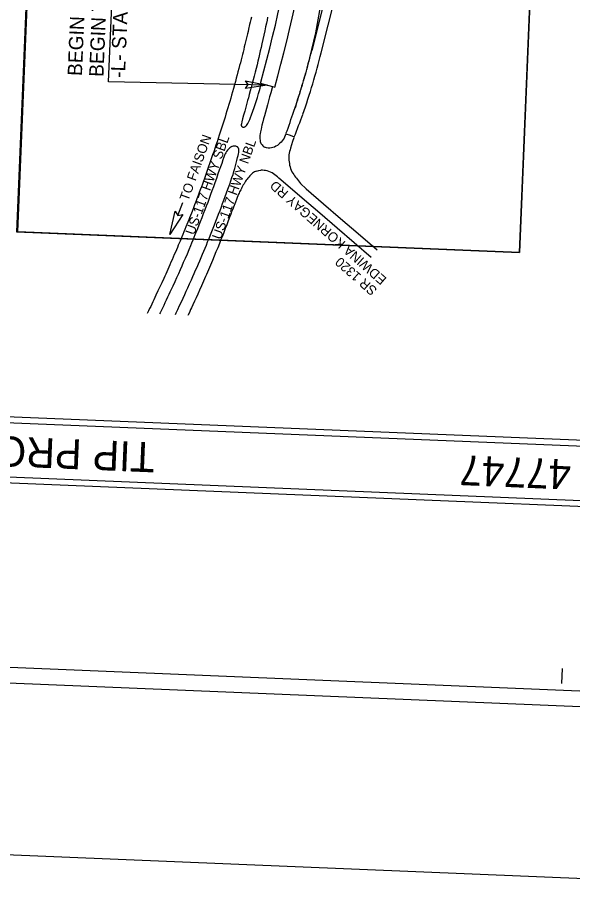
# Model space of a CAD drawing. Extents: x 2264506 to 2267635, y 507918 to 512596.
# Drawn here: x 2265694 to 2266855, y 507918 to 509740 of the extents above; entities that cross this region are included whole.
import ezdxf

# ---------------------------------------------------------------- set-up
doc = ezdxf.new("R2010")
doc.units = 0
for name, color, linetype in [('COGO Default Parcel', 7, 'Continuous'), ('Default', 7, 'Continuous'), ('Exist Structure Minor Drop Inlet Cogo Number', 7, 'Continuous'), ('Matchline', 7, 'Continuous'), ('Prop EOT Dash', 7, 'Continuous'), ('Prop Guardrail', 7, 'Continuous'), ('Prop Horizontal Alignment Station Label', 7, 'Continuous'), ('Prop Horizontal Alignment Tick Label', 7, 'Continuous'), ('Prop Horizontal Alignment Tick Large', 7, 'Continuous'), ('Prop Lane Arrow CELL', 7, 'Continuous'), ('Prop Structure Anchor Unit CELL', 7, 'Continuous'), ('Scratch_Level_1', 7, 'Continuous')]:
    doc.layers.add(name, color=color, linetype=linetype)

msp = doc.modelspace()

# ---------------------------------------------------------------- linework, layer by layer
at = {"layer": 'COGO Default Parcel'}
msp.add_lwpolyline([(2266744.1, 509248.2), (2266800.3, 510607.5), (2265959.7, 510642.3), (2265949.8, 510403.2), (2265738.5, 510412), (2265692.2, 509291.7)], close=True, dxfattribs=at)
at = {"layer": 'Exist Structure Minor Drop Inlet Cogo Number'}
for p, q in [((2265884.5, 509605.1), (2265907.1, 510153.7)), ((2266216, 509598.3), (2265884.5, 509605.1)), ((2266029.4, 509325.8), (2266040.1, 509353))]:
    msp.add_line(p, q, dxfattribs=at)
at = {"layer": 'Matchline'}
msp.add_line((2264698.7, 508031), (2267446.4, 507917.5), dxfattribs=at)
at = {"layer": 'Prop EOT Dash'}
msp.add_lwpolyline([(2265695, 509291.6), (2265813.1, 512149.6), (2266862.2, 512106.3), (2266744.1, 509248.2)], close=True, dxfattribs=at)
at = {"layer": 'Prop Guardrail'}
for p, q in [((2266377.5, 509938.8), (2266309.8, 509670.6)), ((2266329.1, 509665.7), (2266396, 509930.1)), ((2266202.5, 509602), (2266204.4, 509601.5)), ((2266255.5, 509496.7), (2266264.4, 509493.4)), ((2266264.4, 509493.4), (2266272.8, 509490.2))]:
    msp.add_line(p, q, dxfattribs=at)
msp.add_lwpolyline([(2266204.4, 509601.5), (2266227.6, 509595.1), (2266232.4, 509593.8)], dxfattribs=at)
for centre, radius, start, end in [((2262840, 510521.8), 3486, 344.7422, 357.6342), ((2262840, 510521.8), 3517, 344.7004, 357.6342), ((2264768.3, 510060.4), 1590, 341.0347, 345.8113), ((2264768.3, 510060.4), 1610, 341.0347, 345.8113), ((2263436.2, 510359.2), 2868, 344.6915, 344.7422), ((2264763.4, 510046.5), 1590.2, 339.7742, 341.5648), ((2264779.6, 510090), 1609.2, 338.1129, 339.9041)]:
    msp.add_arc(centre, radius, start, end, dxfattribs=at)
at = {"layer": 'Prop Horizontal Alignment Station Label'}
for p, q in [((2266922.1, 508853.6), (2264836.3, 508939.8)), ((2267383.7, 508822), (2264835.8, 508927.3)), ((2266832.4, 508348.1), (2266833.7, 508379.3)), ((2266832.4, 508348.1), (2266833.7, 508379.3))]:
    msp.add_line(p, q, dxfattribs=at)
for points in [[(2264818.2, 508802.9), (2267391, 508696.6)], [(2264818.2, 508802.9), (2267391, 508696.6)], [(2264831.2, 508814.9), (2267379, 508709.6)]]:
    msp.add_lwpolyline(points, dxfattribs=at)
at = {"layer": 'Prop Horizontal Alignment Tick Label'}
msp.add_lwpolyline([(2267406.5, 508310.6), (2267578.5, 512473.3), (2264943, 512582.2), (2264771, 508419.5)], close=True, dxfattribs=at)
at = {"layer": 'Prop Horizontal Alignment Tick Large'}
msp.add_lwpolyline([(2264887.3, 512595.8), (2264713.6, 508389.4), (2267461.2, 508275.9), (2267635, 512482.3)], close=True, dxfattribs=at)
at = {"layer": 'Prop Lane Arrow CELL'}
for p, q in [((2266339.5, 509830.1), (2266317, 509707.7)), ((2266254.7, 509494.8), (2266251.8, 509487)), ((2266251.8, 509487), (2266250, 509484.5)), ((2266269.4, 509480.4), (2266265, 509466.5)), ((2266272.1, 509488.2), (2266269.4, 509480.4))]:
    msp.add_line(p, q, dxfattribs=at)
for points in [[(2266183.1, 509740.4), (2266181.9, 509735), (2266180.7, 509729.8), (2266179.6, 509724.7), (2266177.3, 509715), (2266176.2, 509710.2), (2266175, 509705.1), (2266173.7, 509699.8), (2266172.4, 509694.3), (2266171, 509688.7), (2266169.7, 509683.2), (2266168.4, 509677.8), (2266167.1, 509672.6), (2266165.8, 509667.3), (2266164.4, 509661.9), (2266163, 509656.4), (2266161.6, 509650.8), (2266160.1, 509645), (2266158.6, 509639), (2266156.9, 509632.7), (2266155.2, 509626.1), (2266153.4, 509619.4), (2266151.6, 509612.5), (2266149.7, 509605.5), (2266147.7, 509598.4), (2266145.7, 509591.2), (2266143.7, 509584.2), (2266141.8, 509577.4), (2266139.9, 509570.7), (2266138, 509564.1), (2266136, 509557.5), (2266134.1, 509550.9), (2266132.1, 509544.3), (2266130.1, 509537.8), (2266128.1, 509531.4), (2266126.2, 509525.1), (2266124.2, 509518.9), (2266122.2, 509512.7), (2266120.2, 509506.4), (2266118.1, 509499.9), (2266116, 509493.3), (2266113.8, 509486.5), (2266111.5, 509479.7), (2266109.2, 509472.8), (2266106.8, 509465.9), (2266104.5, 509459), (2266102.2, 509452.4), (2266100, 509446.1), (2266097.9, 509440), (2266095.9, 509434), (2266093.8, 509427.9), (2266091.6, 509421.8), (2266089.4, 509415.5), (2266087.2, 509409.3), (2266085, 509403.2), (2266082.9, 509397.2), (2266080.8, 509391.4), (2266078.6, 509385.5), (2266076.4, 509379.6), (2266074.2, 509373.7), (2266071.9, 509367.7), (2266069.3, 509360.7), (2266067.8, 509356.7), (2266064.4, 509347.9), (2266061.3, 509339.8), (2266057.8, 509330.7), (2266055.9, 509325.9), (2266054, 509321.2), (2266052.2, 509316.4), (2266050.3, 509311.7), (2266048.4, 509306.9), (2266046.3, 509301.9), (2266044.3, 509296.8), (2266042.1, 509291.5), (2266039.9, 509286.3), (2266037.9, 509281.3), (2266034.1, 509272.3), (2266030.4, 509263.5), (2266028.5, 509258.9), (2266026.4, 509254.1), (2266024.3, 509249.2), (2266022, 509244.1), (2266019.8, 509238.9), (2266017.4, 509233.4), (2266015, 509228), (2266012.7, 509222.8), (2266010.5, 509217.8), (2266008.3, 509213), (2266006.2, 509208.2), (2266004, 509203.5), (2266001.9, 509198.8), (2265999.8, 509194.1), (2265995.6, 509185), (2265991.7, 509176.6), (2265987.8, 509168.3), (2265983.6, 509159.2), (2265981.5, 509154.5), (2265979.3, 509149.9), (2265977.1, 509145.2), (2265974.9, 509140.5), (2265972.6, 509135.9), (2265970.4, 509131.2), (2265968.2, 509126.7), (2265966, 509122.1), (2265965.5, 509121.1)], [(2266217.1, 509740.3), (2266215.9, 509734.1), (2266214.5, 509727.4), (2266212.9, 509719.9), (2266211.1, 509711.6), (2266209.2, 509702.4), (2266207.2, 509693.2), (2266205.3, 509684.6), (2266203.5, 509676.8), (2266201.9, 509669.7), (2266200.3, 509662.9), (2266198.6, 509655.7), (2266196.8, 509648.3), (2266195, 509640.7), (2266193, 509632.9), (2266191, 509625), (2266189, 509617.1), (2266186.9, 509609.1), (2266184.8, 509601.2), (2266182.8, 509593.5), (2266180.8, 509586), (2266178.8, 509578.7), (2266177, 509571.9), (2266175.3, 509565.9), (2266173.9, 509560.7), (2266171.5, 509552.1), (2266169.2, 509543.7), (2266166.9, 509535.3), (2266164.8, 509527.8), (2266163.1, 509521.6), (2266162.2, 509517.5), (2266161.9, 509515.4), (2266161.8, 509514.7), (2266161.8, 509514.1), (2266161.9, 509513.6), (2266162, 509513.2), (2266162.2, 509512.8), (2266162.4, 509512.4), (2266162.6, 509512.1), (2266162.9, 509511.8), (2266163.3, 509511.6), (2266163.7, 509511.3), (2266164.8, 509510.8), (2266165.6, 509510.5), (2266165.8, 509510.5), (2266166.4, 509510.4), (2266167.3, 509510.4), (2266167.8, 509510.4), (2266168.3, 509510.5), (2266168.9, 509510.7), (2266169.5, 509511), (2266170.6, 509511.8), (2266171.9, 509512.8), (2266172.6, 509513.4), (2266173.3, 509514.1), (2266174.6, 509516), (2266176, 509518.3), (2266177.2, 509520.8), (2266178.5, 509523.5), (2266179.7, 509526.4), (2266181.2, 509530.4), (2266183.4, 509536.4), (2266186, 509543.7), (2266189, 509551.7), (2266191.7, 509559.5), (2266193.9, 509566.2), (2266195.8, 509572.2), (2266196.7, 509575.2), (2266198.4, 509580.9), (2266200, 509586.6), (2266201.6, 509592.1), (2266203.2, 509597.7), (2266204.2, 509601.5)], [(2266227.4, 509595.2), (2266223.8, 509582.1), (2266221.4, 509573.5), (2266219.1, 509565.2), (2266216.8, 509557), (2266214.6, 509549), (2266212.4, 509541.3), (2266210.3, 509534), (2266208.5, 509527.5), (2266207, 509521.4), (2266205.3, 509514.3), (2266203.4, 509506.3), (2266202.1, 509500.3), (2266201.5, 509496.4), (2266201.1, 509493.4), (2266200.9, 509491), (2266200.8, 509489.3), (2266200.8, 509488.1), (2266201, 509486), (2266201.4, 509483.1), (2266201.8, 509480.6), (2266202.4, 509478.6), (2266203, 509477), (2266203.3, 509476.4), (2266204.2, 509475), (2266205.5, 509473.2), (2266207.2, 509471.2), (2266209.2, 509469.2)], [(2266024.3, 509118.6), (2266025.9, 509122.1), (2266029.5, 509129.7), (2266033.2, 509137.6), (2266036.9, 509145.5), (2266040.4, 509153.1), (2266043.7, 509160.4), (2266047, 509167.5), (2266050.4, 509174.9), (2266054.1, 509183.2), (2266057.7, 509191.3), (2266060.8, 509198.2), (2266063.6, 509204.7), (2266066.6, 509211.3), (2266069.5, 509217.9), (2266072.5, 509224.6), (2266075.4, 509231.3), (2266078.3, 509238.1), (2266081.1, 509244.8), (2266083.8, 509251.2), (2266086.4, 509257.5), (2266089, 509263.7), (2266091.7, 509270.4), (2266094.7, 509277.9), (2266097.7, 509285.4), (2266100.5, 509292.3), (2266103.2, 509299), (2266105.9, 509306.2), (2266108.8, 509313.6), (2266111.7, 509321.1), (2266114.7, 509328.7), (2266117.6, 509336.2), (2266120.4, 509343.6), (2266123.1, 509350.8), (2266125.7, 509358.1), (2266128.6, 509365.7), (2266131.4, 509373.3), (2266134, 509380.5), (2266135.3, 509383.9), (2266137.8, 509391), (2266140.3, 509398.3), (2266142.6, 509405.1), (2266144.8, 509411.6), (2266146.7, 509417.9), (2266148.4, 509424), (2266149.9, 509429.7), (2266151.3, 509435.1), (2266152.8, 509440.8), (2266154.3, 509446.7), (2266155.4, 509451.4), (2266156.2, 509454.8), (2266156.7, 509457.7), (2266157, 509460), (2266157.1, 509462.1), (2266157, 509463.9), (2266156.9, 509464.7), (2266156.7, 509465.4), (2266156.5, 509466), (2266155.9, 509467.1), (2266155.2, 509468.1), (2266154.8, 509468.6), (2266154.3, 509469), (2266153.7, 509469.4), (2266152.3, 509470), (2266151, 509470.5), (2266150.4, 509470.7), (2266149.7, 509470.8), (2266149, 509470.9), (2266147.2, 509470.8), (2266145.2, 509470.6), (2266143.2, 509470), (2266142.2, 509469.6), (2266141.2, 509469.2), (2266140.3, 509468.6), (2266138.4, 509467.3), (2266136.7, 509465.7), (2266135.1, 509464), (2266133.3, 509461.9), (2266131.4, 509459.4), (2266129.8, 509457), (2266128.6, 509454.7), (2266127.3, 509451.6), (2266125.6, 509447.4), (2266123.6, 509441.7), (2266121.1, 509434.6), (2266118.6, 509427.6), (2266116.1, 509420.6), (2266113.2, 509412.5), (2266110, 509403.1), (2266106.8, 509394), (2266103.7, 509385.3), (2266100.8, 509377.1), (2266098, 509369.3), (2266095, 509361.3), (2266091.9, 509353.2), (2266088.8, 509345.2), (2266085.7, 509337.3), (2266082.6, 509329.1), (2266079.4, 509320.7), (2266076.3, 509312.8), (2266073.4, 509305.4), (2266070.4, 509297.8), (2266067.1, 509289.9), (2266065.2, 509285.2), (2266063, 509279.9), (2266060.6, 509274), (2266058.2, 509268.1), (2266056, 509262.7), (2266052.2, 509253.7), (2266048.6, 509245.3), (2266044.7, 509236.2), (2266040.8, 509227.3), (2266037.5, 509219.6), (2266034.2, 509212.2), (2266030.6, 509204), (2266026.7, 509195.4), (2266022.8, 509186.9), (2266018.9, 509178.4), (2266015, 509170), (2266012.9, 509165.6), (2266010.6, 509160.6), (2266008, 509155.1), (2266005.2, 509149.2), (2266002.4, 509143.2), (2265999.9, 509138), (2265995.8, 509129.5), (2265992.2, 509122.2), (2265991.2, 509120)], [(2266209.2, 509469.2), (2266209.2, 509469.2), (2266210.5, 509468.8)], [(2266193.9, 509418.5), (2266191.8, 509417.7), (2266189.5, 509416.7), (2266187.3, 509415.5), (2266185.5, 509414.3), (2266183.8, 509412.8), (2266181.8, 509410.8), (2266179.7, 509408.5), (2266177.7, 509406.1), (2266175.7, 509403.7), (2266174.1, 509401.6), (2266172.6, 509399.6), (2266171, 509397.3), (2266169.4, 509394.8), (2266167.8, 509392.2), (2266166.3, 509389.6), (2266164.9, 509387), (2266163.5, 509384.5), (2266162.2, 509382), (2266160.9, 509379.6), (2266159.8, 509377.3), (2266158.6, 509374.9), (2266157.5, 509372.5), (2266156.4, 509370), (2266155.2, 509367), (2266153.8, 509363.6), (2266152.1, 509359.3), (2266149.9, 509353.7), (2266147, 509346.4), (2266143.7, 509337.9), (2266141.9, 509333.2), (2266140.1, 509328.3), (2266138.3, 509323.5), (2266134.9, 509314.5), (2266131.8, 509306.4), (2266128.7, 509298.3), (2266125.5, 509290.1), (2266122.5, 509282.5), (2266119.6, 509275.4), (2266116.4, 509267.3), (2266112.7, 509258.3), (2266109.1, 509249.5), (2266105.7, 509241.1), (2266101.9, 509231.9), (2266099.8, 509226.9), (2266097.7, 509221.9), (2266095.6, 509217), (2266093.6, 509212.2), (2266091.6, 509207.5), (2266089.5, 509202.8), (2266087.5, 509198), (2266085.3, 509193.2), (2266083.1, 509188.3), (2266080.9, 509183.4), (2266078.8, 509178.6), (2266074.7, 509169.5), (2266071, 509161.2), (2266067.7, 509153.8), (2266064.4, 509146.7), (2266060.8, 509139.1), (2266057.7, 509132.6), (2266056.1, 509129.1), (2266054.2, 509125.3), (2266050.8, 509117.8), (2266050.6, 509117.5)], [(2266193.9, 509418.5), (2266198.9, 509419.5), (2266203.3, 509420.4)], [(2266434, 509238), (2266398.3, 509268.5), (2266362.3, 509299.5), (2266326.6, 509330.3), (2266289.5, 509362.1), (2266259.2, 509388), (2266240.4, 509404)], [(2266279.3, 509400.9), (2266285.8, 509392.6), (2266298, 509381.3), (2266334, 509350.3), (2266369.7, 509319.7), (2266406.6, 509288.1), (2266446.4, 509253.8)]]:
    msp.add_lwpolyline(points, dxfattribs=at)
for points in [[(2266317, 509707.7), (2266306.1, 509661.1), (2266300, 509636.9), (2266296.8, 509624.8), (2266293.4, 509612.8), (2266286.6, 509589.9), (2266279.6, 509567), (2266274.7, 509551)], [(2266250, 509484.5), (2266240.2, 509474.2), (2266228.4, 509467.6), (2266215.1, 509467.1), (2266210.5, 509468.8)], [(2266265, 509466.5), (2266261.7, 509452.5), (2266262.1, 509437.7), (2266265.1, 509423.7), (2266271.8, 509411.2), (2266279.3, 509400.9)], [(2266240.4, 509404), (2266229.7, 509412.6), (2266216.1, 509418.9), (2266203.3, 509420.4)]]:
    msp.add_spline(points, degree=3, dxfattribs=at)
at = {"layer": 'Scratch_Level_1'}
for points in [[(2266171.2, 509607), (2266216, 509598.3), (2266170.6, 509591.2), (2266176.5, 509599.1)], [(2266039.5, 509328.1), (2266012.5, 509286), (2266023.8, 509335), (2266029.4, 509325.8)]]:
    msp.add_lwpolyline(points, close=True, dxfattribs=at)

# ---------------------------------------------------------------- texts
at = {"layer": 'Default'}
for s, rotation, p in [('TO FAISON', 70.1637, (2266051.2, 509354.6)), ('US-117 HWY SBL', 70.1637, (2266063.5, 509283.6)), ('US-117 HWY NBL', 70.1637, (2266119, 509274.1)), ('EDWINA KORNEGAY RD', 138.6772, (2266467.5, 509194.2)), ('SR 1320 ', 138.6772, (2266447.7, 509171.6))]:
    msp.add_text(s, height=20, rotation=rotation, dxfattribs=at).set_placement(p)
at = {"layer": 'Prop Horizontal Alignment Station Label'}
for s, p in [('TIP PROJECT:', (2265982.5, 508851.4)), ('47747', (2266852.5, 508815.5))]:
    msp.add_text(s, height=62.5, rotation=177.6342, dxfattribs=at).set_placement(p)
at = {"layer": 'Prop Structure Anchor Unit CELL'}
for s, p in [('BEGIN TIP PROJECT B-5981', (2265873.7, 509614.9)), ('BEGIN CONSTRUCTION,', (2265828.8, 509616.8)), ('-L- STA. 13+20.00', (2265918.7, 509613))]:
    msp.add_text(s, height=30, rotation=87.6342, dxfattribs=at).set_placement(p)

doc.saveas('drawing.dxf')
